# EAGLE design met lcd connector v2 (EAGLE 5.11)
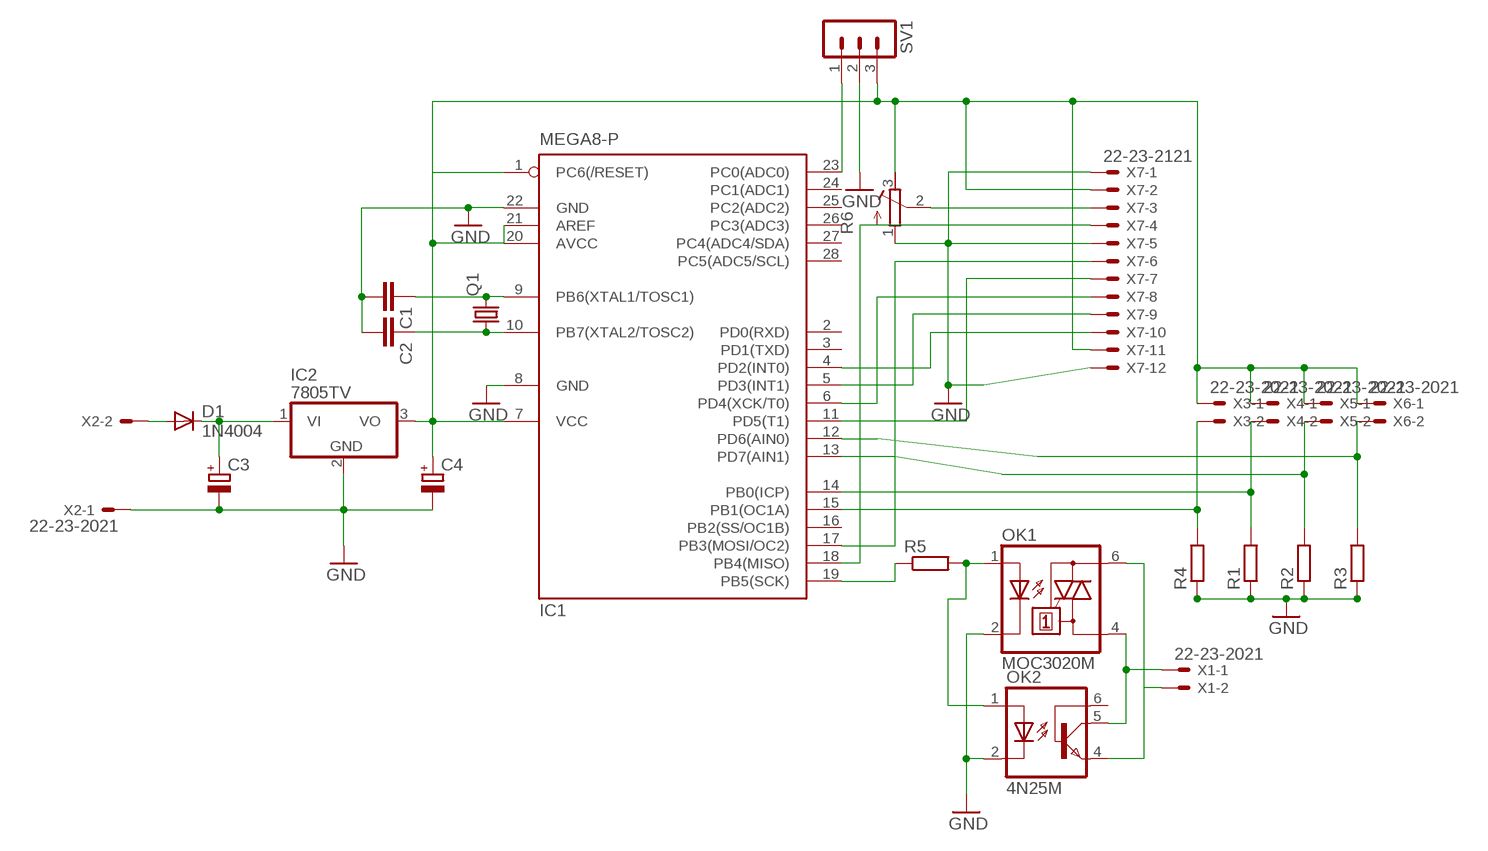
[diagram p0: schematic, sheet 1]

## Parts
C1  C2.5/2  [C2.5-2]
C2  C2.5/2  [C2.5-2]
C3  CPOL-EUE2-4  [E2-4]
C4  CPOL-EUE2-4  [E2-4]
D1  1N4004  [DO41-10]
IC1  MEGA8-P  [DIL28-3]
IC2  7805TV  [TO220V]
OK1  MOC3020M  [DIL06]
OK2  4N25M  [DIL06]
Q1  CRYSTALHC49S  [HC49/S]
R1  R-EU_0207/10  [0207/10]
R2  R-EU_0207/10  [0207/10]
R3  R-EU_0207/10  [0207/10]
R4  R-EU_0207/10  [0207/10]
R5  R-EU_0207/10  [0207/10]
R6  R-TRIMM3339P  [RTRIM3339P]
SV1  MA03-1  [MA03-1]
X1  22-23-2021  [22-23-2021]
X2  22-23-2021  [22-23-2021]
X3  22-23-2021  [22-23-2021]
X4  22-23-2021  [22-23-2021]
X5  22-23-2021  [22-23-2021]
X6  22-23-2021  [22-23-2021]
X7  22-23-2121  [22-23-2121]

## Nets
GND: C1.2 C2.2 C3.- C4.- IC1.8(GND) IC1.22(GND) IC2.2(GND) OK1.2(C) OK2.2(C) R1.1 R2.1 R3.1 R4.1 R6.1(E) SV1.2 X2.1 X7.1 X7.5 X7.12
N$1: IC1.13(PD7(AIN1)) R2.2 X5.2
N$2: OK1.1(A) OK2.1(A) R5.2
N$3: IC1.19(PB5(SCK)) R5.1
N$4: IC1.18(PB4(MISO)) X7.4
N$5: C1.1 IC1.9(PB6(XTAL1/TOSC1)) Q1.2
N$6: C2.1 IC1.10(PB7(XTAL2/TOSC2)) Q1.1
N$7: OK1.4(A1) OK2.5(COL) X1.1
N$8: OK1.6(A2) OK2.4(EMI) X1.2
N$9: IC1.15(PB1(OC1A)) R4.2 X3.2
N$10: IC1.14(PB0(ICP)) R1.2 X4.2
N$11: C3.+ D1.C IC2.1(VI)
N$12: IC1.12(PD6(AIN0)) R3.2 X6.2
N$13: R6.2(S) X7.3
N$14: C4.+ IC1.1(PC6(/RESET)) IC1.7(VCC) IC1.20(AVCC) IC1.21(AREF) IC2.3(VO) R6.3(A) SV1.3 X3.1 X4.1 X5.1 X6.1 X7.2 X7.11
N$15: IC1.17(PB3(MOSI/OC2)) X7.6
N$16: IC1.4(PD2(INT0)) X7.10
N$17: IC1.5(PD3(INT1)) X7.9
N$18: IC1.6(PD4(XCK/T0)) X7.8
N$19: IC1.11(PD5(T1)) X7.7
N$20: D1.A X2.2
N$21: IC1.23(PC0(ADC0)) SV1.1
Unconnected: IC1.2(PD0(RXD)) IC1.3(PD1(TXD)) IC1.16(PB2(SS/OC1B)) IC1.24(PC1(ADC1)) IC1.25(PC2(ADC2)) IC1.26(PC3(ADC3)) IC1.27(PC4(ADC4/SDA)) IC1.28(PC5(ADC5/SCL)) OK2.6(BAS)

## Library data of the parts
C1 C2 = capacitor-wima:C: CAPACITOR
C3 C4 = rcl:CPOL-EU: POLARIZED CAPACITOR, European symbol
D1 = diode:1N4004: DIODE
IC1 = atmel:MEGA8-P: MICROCONTROLLER 8 Kbytes FLASH, 1 kbytes SRAM, 512 bytes EEPROM, USART, 4-channel 10 bit ADC, 2-channel 8 bit ADC Pin compatible with Atmega48, ATMega88, ATMega168 Source: avr.lbr; OC_FARNELL: unknown; OC_NEWARK: unknown
IC2 = linear:78*: Positive VOLTAGE REGULATOR Source: http://cache.national.com/ds/LM/LM78L05.pdf http://www.fairchildsemi.com/ds/LM/LM7805.pdf
OK1 = optocoupler:MOC30*M: RANDOM-PHASE OPTOISOLATORS TRIAC DRIVER OUTPUT Source: http://www.fairchildsemi.com MOC3020-M.pdf; MF: FAIRCHILD SEMICONDUCTOR; MPN: MOC3020-M; OC_FARNELL: 1505425; OC_NEWARK: 72K8895
OK2 = optocoupler:4N*?M: General Purpose 6-Pin Phototransistor Optocouplers Source: http://www.fairchildsemi.com/ds/4N/4N35-M.pdf; MPN: 4N25-M; OC_FARNELL: 1021349; OC_NEWARK: 98K9084
Q1 = crystal:CRYSTAL: CRYSTAL; OC_FARNELL: 1667008; OC_NEWARK: unknown
R1-R5 = resistor:R-EU_: RESISTOR, European symbol
R6 = rcl:R-TRIMM: Trimm resistor
SV1 = con-lstb:MA03-1: PIN HEADER; OC_FARNELL: unknown; OC_NEWARK: unknown
X1-X6 = con-molex:22-23-2021: .100" (2.54mm) Center Header - 2 Pin; MF: MOLEX; MPN: 22-23-2021; OC_FARNELL: 1462926; OC_NEWARK: 25C3832
X7 = con-molex:22-23-2121: .100" (2.54mm) Center Header - 12 Pin; MF: MOLEX; MPN: 22-23-2121; OC_FARNELL: 1462935; OC_NEWARK: 56H0456

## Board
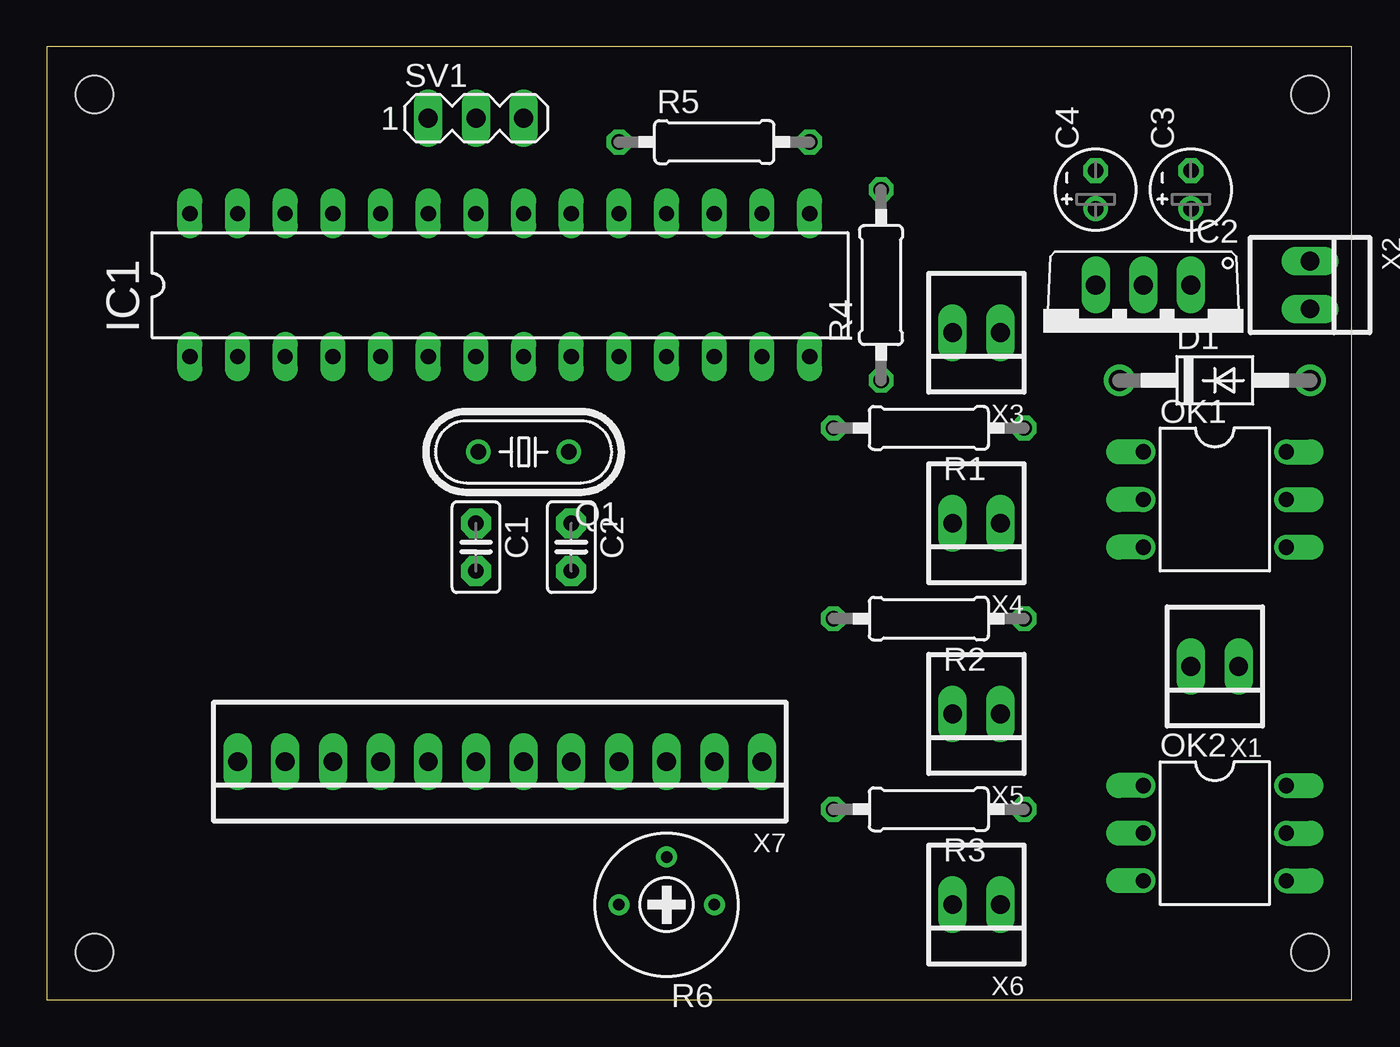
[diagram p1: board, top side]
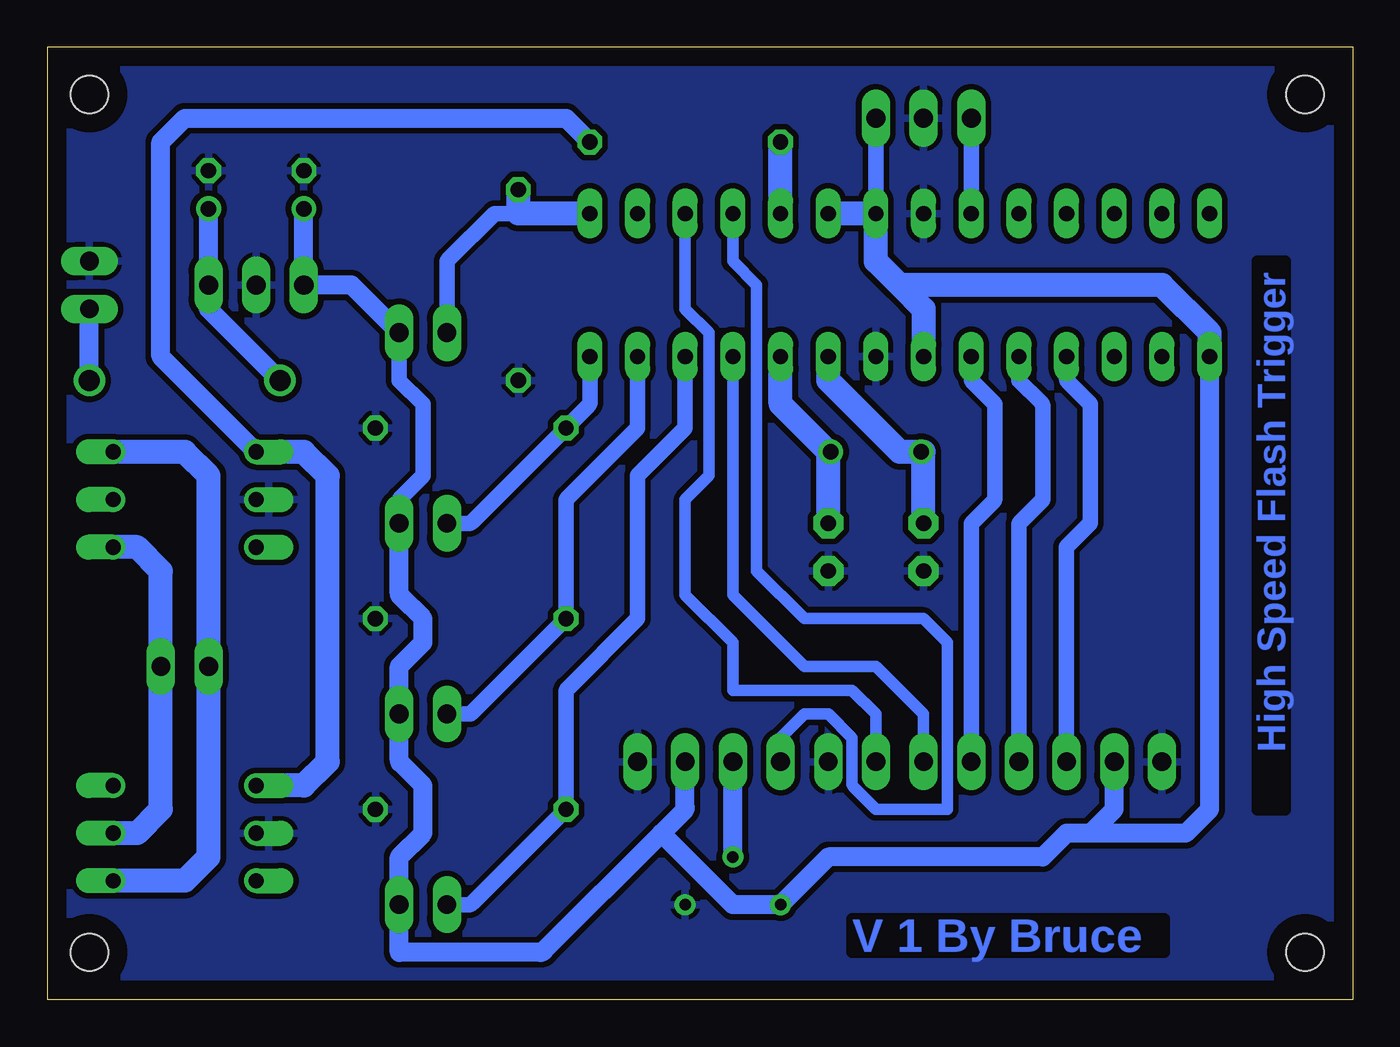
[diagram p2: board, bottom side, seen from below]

Size 69.52 x 50.79 mm. Coordinates in mm from the lower left corner, seen from the top.
Outline: 0,0 69.52,0 69.52,50.79 0,50.79 0,0
Copper layers (1*16): Top 0.035mm / dielectric 1.5mm / Bottom 0.035mm
Design rules "default": minimum track width 10mil, minimum drill 24mil, track to track 8mil, track to pad 8mil, pad to pad 8mil, via to via 8mil, smd to smd 8mil, copper to edge 40mil, drill to drill 8mil, minimum pad ring 10mil, minimum via ring 8mil, stop-mask expansion 4mil, vias tented up to drill 0mil, thermal gap 10mil
Holes 2 mm at 2.54,48.26 2.54,2.54 67.31,2.54 67.31,48.26

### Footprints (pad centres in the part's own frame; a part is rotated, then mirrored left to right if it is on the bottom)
C2.5-2 = drill 0.813 pad 1.6 octagon: 1 -1.27,0; 2 1.27,0
E2-4 = drill 0.813 pad 1.27 round: + -1.016,0 | drill 0.813 pad 1.27 octagon: - 1.016,0
DO41-10 = drill 1.118 round: A 5.08,0; C -5.08,0
DIL28-3 = drill 0.813 long: 1 -16.51,-3.81; 2 -13.97,-3.81; 3 -11.43,-3.81; 4 -8.89,-3.81; 5 -6.35,-3.81; 6 -3.81,-3.81; 7 -1.27,-3.81; 8 1.27,-3.81; 9 3.81,-3.81; 10 6.35,-3.81; 11 8.89,-3.81; 12 11.43,-3.81; 13 13.97,-3.81; 14 16.51,-3.81; 15 16.51,3.81; 16 13.97,3.81; 17 11.43,3.81; 18 8.89,3.81; 19 6.35,3.81; 20 3.81,3.81; 21 1.27,3.81; 22 -1.27,3.81; 23 -3.81,3.81; 24 -6.35,3.81; 25 -8.89,3.81; 26 -11.43,3.81; 27 -13.97,3.81; 28 -16.51,3.81
TO220V = drill 1.016 long: 1 -2.54,-2.54; 2 0,-2.54; 3 2.54,-2.54
DIL06 = drill 0.813 offset: 1 -2.54,-3.81; 2 0,-3.81; 3 2.54,-3.81; 4 2.54,3.81; 5 0,3.81; 6 -2.54,3.81
HC49/S = drill 0.813 round: 1 -2.413,0; 2 2.413,0
0207/10 = drill 0.813 octagon: 1 -5.08,0; 2 5.08,0
RTRIM3339P = drill 0.61 round: 1 -2.54,0; 2 0,-2.54; 3 2.54,0
MA03-1 = drill 1.016 long: 1 -2.54,0; 2 0,0; 3 2.54,0
22-23-2021 = drill 1 long: 1 -1.27,0; 2 1.27,0
22-23-2121 = drill 1 long: 1 -13.97,0; 2 -11.43,0; 3 -8.89,0; 4 -6.35,0; 5 -3.81,0; 6 -1.27,0; 7 1.27,0; 8 3.81,0; 9 6.35,0; 10 8.89,0; 11 11.43,0; 12 13.97,0

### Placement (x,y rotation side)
C1  22.86,24.13 270 top
C2  27.94,24.13 270 top
C3  60.96,43.18 90 top
C4  55.88,43.18 90 top
D1  62.23,33.02 0 top
IC1  24.13,38.1 0 top
IC2  58.42,35.56 180 top
OK1  62.23,26.67 270 top
OK2  62.23,8.89 270 top
Q1  25.4,29.21 180 top
R1  46.99,30.48 180 top
R2  46.99,20.32 180 top
R3  46.99,10.16 180 top
R4  44.45,38.1 90 top
R5  35.56,45.72 0 top
R6  33.02,5.08 180 top
SV1  22.86,46.99 0 top
X1  62.23,17.78 180 top
X2  67.31,38.1 270 top
X3  49.53,35.56 180 top
X4  49.53,25.4 180 top
X5  49.53,15.24 180 top
X6  49.53,5.08 180 top
X7  24.13,12.7 180 top

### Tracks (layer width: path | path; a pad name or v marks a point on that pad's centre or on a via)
GND
  pour Bottom (isolate 0.305): 0,50.8 0,0 69.85,0 69.85,50.8
N$1
  Bottom 0.813: X5.2 47.09,15.24 arc-45 46.92,15.31 R2.2 41.91,26.57 arc45 41.84,26.74 38.1,30.48 IC1.13
N$2
  Bottom 1.016: OK1.1 63.5,34.29 63.5,45.72 62.23,46.99 41.91,46.99 R5.2
  Bottom 1.27: OK1.1 55.88,29.21 54.61,27.94 54.61,12.7 55.88,11.43 OK2.1
N$3
  Bottom 1.27: IC1.19 R5.1
N$4
  Bottom 0.61: IC1.18 33.02,39.37 31.75,38.1 31.75,22.86 29.21,20.32 22.86,20.32 21.59,19.05 21.59,10.16 25.4,10.16 26.6,11.36 arc45 26.67,11.54 26.67,13.97 27.94,15.24 29.21,15.24 30.41,14.04 arc-45 30.48,13.87 X7.4
N$5
  Bottom 1.27: C1.1 22.86,29.21 Q1.2 24.13,29.21 27.94,33.02 IC1.9
N$6
  Bottom 0.813: 27.94,29.21 Q1.1
  Bottom 1.27: C2.1 27.94,29.21 30.48,31.75 IC1.10
N$7
  Bottom 1.27: OK2.5 64.77,8.89 63.5,10.16 X1.1 63.5,22.86 64.77,24.13 OK1.4
N$8
  Bottom 1.27: OK2.4 62.23,6.35 60.96,7.62 X1.2 60.96,27.94 62.23,29.21 OK1.6
N$9
  Bottom 0.813: X3.2 48.26,39.27 arc45 48.19,39.44 45.72,41.91 44.45,41.91
  Bottom 1.27: IC1.15 44.45,41.91 R4.2
N$10
  Bottom 0.813: X4.2 47.09,25.4 arc-45 46.92,25.47 R1.2 40.71,31.68 arc-45 40.64,31.86 IC1.14
N$11
  Bottom 1.016: C3.+ IC2.1 60.96,36.83 D1.C
N$12
  Bottom 0.813: X6.2 47.09,5.08 arc-45 46.92,5.15 R3.2 41.91,16.41 arc45 41.84,16.58 38.1,20.32 38.1,27.94 35.56,30.48 IC1.12
N$13
  Bottom 1.016: R6.2 X7.3
N$14
  Bottom 0.813: X4.1 50.8,26.57 arc45 50.73,26.74 49.53,27.94 49.53,31.75 50.8,33.02 X3.1 | IC1.21 SV1.3
  Bottom 1.016: X4.1 50.8,21.7 arc-45 50.73,21.52 49.53,20.32 49.53,19.16 arc45 49.6,18.98 50.8,17.78 X5.1 50.8,12.8 arc-45 50.73,12.63 49.53,11.43 49.53,8.89 50.8,7.62 X6.1 50.8,2.54 43.28,2.54 arc-45 43.11,2.61 36.83,8.89 | 36.83,8.89 33.02,5.08 R6.3 27.94,7.62 16.51,7.62 15.24,8.89 13.97,8.89 | 36.83,8.89 35.63,10.09 arc-45 35.56,10.27 X7.2 | X7.11 12.7,10.16 13.97,8.89 | 13.97,8.89 8.89,8.89 7.62,10.16 IC1.1 | X3.1 53.34,38.1 IC2.3 C4.+
  Bottom 1.27: IC1.20 IC1.21 25.4,39.37 24.13,38.1 | 24.13,38.1 10.16,38.1 7.62,35.56 IC1.1 | IC1.7 22.86,36.83 24.13,38.1
N$15
  Bottom 0.61: IC1.17 35.56,36.83 34.29,35.56 34.29,27.94 35.56,26.67 35.56,21.59 33.02,19.05 33.02,16.51 26.67,16.51 25.4,15.24 X7.6
N$16
  Bottom 0.813: IC1.4 15.24,33.12 arc-45 15.17,32.95 13.97,31.75 13.97,25.5 arc45 14.04,25.33 15.24,24.13 X7.10
N$17
  Bottom 0.813: X7.9 17.78,25.3 arc45 17.71,25.47 16.51,26.67 16.51,31.64 arc-45 16.58,31.82 17.78,33.02 IC1.5
N$18
  Bottom 0.813: IC1.6 20.32,33.12 arc-45 20.25,32.95 19.05,31.75 19.05,26.77 arc45 19.12,26.6 20.32,25.4 X7.8
N$19
  Bottom 0.61: X7.7 22.86,15.24 25.4,17.78 29.21,17.78 33.02,21.59 IC1.11
N$20
  Bottom 1.016: D1.A X2.2
N$21
  Bottom 0.813: IC1.23 SV1.1

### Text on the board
Bottom: High Speed Flash Trigger | V 1 By Bruce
